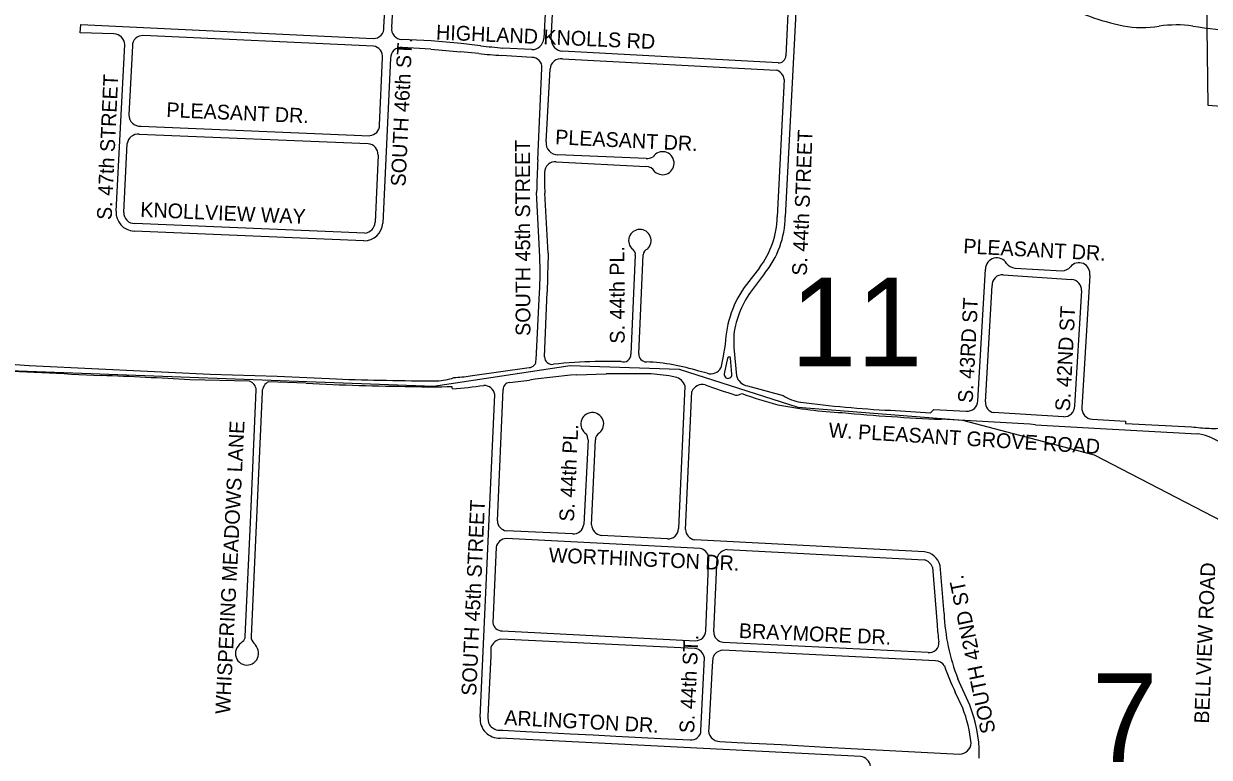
# Model space of a CAD drawing. Extents: x 0 to 712119, y 0 to 761125.
# Drawn here: x 668176 to 672194, y 717234 to 719721 of the extents above; entities that cross this region are included whole.
import ezdxf

# ---------------------------------------------------------------- set-up
doc = ezdxf.new("R2010")
doc.units = 0
for name, color, linetype in [('PAVED ROADS', 7, 'Continuous'), ('Priority 10', 7, 'Continuous'), ('Priority 11', 7, 'Continuous'), ('Priority 7', 7, 'Continuous'), ('street names', 7, 'Continuous')]:
    doc.layers.add(name, color=color, linetype=linetype)

msp = doc.modelspace()

# ---------------------------------------------------------------- linework, layer by layer
at = {"layer": 'PAVED ROADS'}
for points in [[(669397, 719709.4), (669403.4, 719825.1), (669409.6, 719943.3)], [(669423.3, 719708.6), (669436.1, 719940.9)], [(669951.4, 719905.7), (669938.5, 719670.6)], [(669963.9, 719668.3), (669975.8, 719905.8)], [(670795.5, 719831.4), (670791.3, 719737.7), (670757.2, 719066.8)], [(670769.2, 719827.4), (670759.6, 719612.3)], [(668481.8, 719686.4), (668368, 719690.6), (668369.4, 719718.6), (669360.9, 719671.4)], [(669361.5, 719644.8), (668581, 719680.8)], [(669556.9, 719663.2), (669457.9, 719667.3)], [(668489, 719085.5), (668519, 719650.2)], [(668544.5, 719646.3), (668532.6, 719412.3)], [(668544.5, 719646.3), (668544.5, 719646.3)], [(669556.2, 719635.2), (669459, 719640.1)], [(669718.6, 719619.8), (669657, 719626.1)], [(669724.8, 719646.3), (669659.2, 719653.9)], [(669898, 719633.6), (669800.2, 719637.9)], [(670733.1, 719588.5), (670002.2, 719627.7)], [(669382.2, 719376.8), (669391.9, 719605.6)], [(669419.3, 719603.8), (669392.9, 719044.7)], [(669898, 719606.4), (669795.6, 719613.4)], [(670002, 719601.7), (670726, 719563.8)], [(669918.4, 719259.3), (669932.2, 719570.8)], [(669946.7, 719320.5), (669960.1, 719567.8)], [(670753.7, 719531.7), (670730.1, 719066.4)], [(668567.6, 719346.5), (669343.2, 719314.4)], [(668573.6, 719373.9), (669349.2, 719341.5)], [(668515.6, 719081.5), (668527.2, 719314.5)], [(669377.1, 719275.4), (669367.4, 719047.8)], [(670285.3, 719264.1), (669986.3, 719277)], [(669981.2, 719253.3), (670284.9, 719237.4)], [(669925.5, 718930.3), (669914.2, 719149.3)], [(669953.8, 718943.7), (669942.5, 719146.9)], [(669329, 718984.6), (668550.1, 719017.8)], [(669332.7, 719011), (668552.2, 719044)], [(670248.9, 718936.7), (670233.9, 718601)], [(670240.1, 718956.3), (670240.1, 718956.3)], [(670261.1, 718602.3), (670275.5, 718937.8)], [(670670.2, 718893.8), (670625.8, 718837.5)], [(670686.6, 718874), (670645.8, 718820)], [(671410, 718442.8), (671435.2, 718889.4)], [(671496, 718869.9), (671727.6, 718853.6)], [(671535.1, 718892.6), (671696, 718883.8)], [(671788.9, 718867.9), (671762.2, 718420.6)], [(671435.7, 718438.9), (671458.2, 718833.1)], [(671761.1, 718816.3), (671737.9, 718425.5)], [(669912.4, 718581.8), (669924.7, 718809.9)], [(669941.1, 718591.9), (669950.3, 718810.7)], [(670583, 718667.9), (670583, 718623.3), (670591.3, 718527.6)], [(670554, 718634.2), (670545.5, 718588), (670538.6, 718555)], [(670200.6, 718575.5), (670112.9, 718575.9), (670112.9, 718575.9)], [(670561.6, 718587.8), (670550.4, 718534.2)], [(670576.6, 718532.7), (670571.5, 718587.2)], [(668808.3, 718533.2), (669035.2, 718526.3), (669235.9, 718516.8)], [(669688.9, 718527.1), (669888.8, 718555.5)], [(670049.1, 718531), (670150, 718534.7)], [(670492.7, 718536.3), (670464.4, 718543.6)], [(668941.6, 718509.1), (668739.4, 718514)], [(669133.9, 718502.4), (669006.3, 718507.6)], [(669822.6, 718504.3), (669890, 718513.1)], [(670417.3, 718492.4), (670395.4, 718009.4)], [(670628.6, 718493), (670749.6, 718460.9)], [(668926.5, 717644), (668944.7, 718029.8), (668964, 718479.5)], [(668984.2, 718473), (668947, 717643.5)], [(669723, 717369.7), (669772.3, 718464.5)], [(669781.4, 718035.7), (669800.8, 718481.4)], [(670418.9, 718006.6), (670440.4, 718474.8)], [(671249.8, 718401.8), (671260.5, 718413.4), (671370.6, 718407.9)], [(671113.5, 718410.5), (671249.8, 718401.8), (671249.8, 718401.8), (671249.8, 718401.8), (671249.8, 718401.8)], [(671699.8, 718388.7), (671463.2, 718402.6)], [(671797, 718380.6), (671909.7, 718373.4), (671910.4, 718365.6), (672134, 718354.3)], [(671605.7, 718361.8), (671785.3, 718351.4), (672152.6, 718330.7)], [(670088.9, 718310), (670074.2, 718023)], [(670100.9, 718022.4), (670113.5, 718310.6)], [(670468.9, 717942.5), (669811.5, 717976.2)], [(670036.1, 717991.5), (669811.7, 718002.1)], [(670357.8, 717975.2), (670133.1, 717986.7)], [(671228.7, 717930.9), (670450.1, 717971.1)], [(669777, 717946.2), (669765.6, 717690.3)], [(670560.2, 717938.4), (671227.7, 717903.7)], [(670488.2, 717663.3), (670498.4, 717912.6)], [(670514.6, 717659.4), (670525.8, 717912.2)], [(671255.6, 717879.2), (671271.6, 717683)], [(671295.4, 717722.2), (671281.6, 717885.1)], [(669797.4, 717662.6), (670453, 717629.4)], [(669797.4, 717662.6), (669797.4, 717662.6)], [(668914, 717623.5), (668918, 717627)], [(670451.2, 717603.3), (669793.5, 717635.2)], [(671240.9, 717589.9), (670547.1, 717624.1)], [(669759.8, 717606.5), (669759, 717577.3), (669749.5, 717374.7)], [(670471.5, 717325.1), (670482.9, 717572)], [(670511.5, 717571.4), (670509.6, 717543.8), (670497.9, 717332.7)], [(671266.2, 717561.9), (670544.2, 717597.1)], [(671382.2, 717410.7), (671342.1, 717500.8)], [(671358.5, 717401), (671333.2, 717455.4)], [(669787.7, 717325.9), (669800, 717325.9), (669878.1, 717322.1), (669945.4, 717318.7), (670029.3, 717314.1), (670106.1, 717310.4), (670183, 717305.8), (670334.9, 717298.4), (670434.3, 717293.4)], [(671012.7, 717237.1), (669791.1, 717299.1)], [(670535.9, 717288.1), (670594.2, 717284.9), (670668.8, 717281.7), (670743.7, 717277.3), (670818.9, 717273.1), (670893.1, 717268.9), (670980.9, 717264.8), (671347.3, 717245.3)], [(670535.9, 717288.1), (670535.9, 717288.1), (670535.9, 717288.1)]]:
    msp.add_lwpolyline(points, dxfattribs=at)
for centre, radius, start, end in [((672072.9, 720538.1), 841.7, 242.1615, 258.2988), ((669363, 719705.5), 34.2, 266.4728, 6.5311), ((669459.2, 719703.5), 36.3, 171.9329, 267.8384), ((671966.8, 720057), 349.2, 259.3393, 279.4982), ((672083.2, 719313.5), 403.4, 82.1403, 98.3758), ((672386.7, 721280), 1586.4, 260.9958, 266.6809), ((668480.1, 719647.4), 39.1, 4.1097, 87.4028), ((668579.6, 719645.8), 35.1, 87.7503, 179.0986), ((669250.5, 715746.1), 3929, 84.0292, 85.5278), ((669898.8, 719673.3), 39.8, 268.8332, 356.0572), ((670004, 719667.8), 40.1, 179.2599, 267.489), ((669357.4, 719610.2), 34.9, 352.3842, 83.2013), ((669454.8, 719604.8), 35.5, 83.3228, 181.6046), ((670126.7, 725423.7), 5816.5, 264.37163, 265.3677), ((669888.2, 721184.4), 1573.8, 263.8127, 266.6246), ((670873.6, 729634), 10053.5, 263.43886, 263.87095), ((669899.6, 719573.7), 32.7, 354.7849, 92.7415), ((669996.7, 719565.5), 36.6, 81.6269, 176.3044), ((670734.6, 719613.5), 25, 266.6118, 357.4416), ((670716.2, 719527.3), 37.8, 6.7363, 74.9993), ((668570.2, 719411.4), 37.7, 178.6619, 275.0855), ((669346.3, 719377.3), 35.9, 274.6012, 359.1598), ((668563.7, 719309.9), 36.8, 83.9311, 172.8665), ((669340.2, 719277.5), 37, 356.85, 85.2205), ((669986, 719316.4), 39.5, 173.9806, 270.5043), ((681511.5, 718755.3), 11604, 177.5108, 178.05438), ((670286.6, 719310.3), 46.2, 268.3597, 298.9214), ((670341.4, 719248.2), 39, 227.8607, 146.414), ((670489, 719189.8), 548.2, 177.1552, 184.489), ((669977.4, 719217.5), 36, 84.0452, 180.7246), ((670282.6, 719199.1), 38.4, 31.778, 86.6573), ((668553.7, 719082.5), 64.8, 177.3558, 266.8147), ((668550.5, 719078.9), 34.9, 175.7004, 272.812), ((670426.6, 719075), 303.6, 323.3638, 358.3665), ((670446.3, 719071.3), 310.9, 320.6177, 359.1673), ((669328.7, 719048.9), 64.3, 270.2466, 356.234), ((669328, 719050.1), 39.4, 276.8577, 356.5972), ((670264.3, 718985.6), 38, 311.9511, 230.3577), ((675761.7, 718725.8), 5812, 177.85112, 179.16277), ((670229.7, 718939.8), 19.5, 350.7912, 57.86), ((670297, 718937), 21.5, 109.6388, 177.9251), ((668349.4, 718881.1), 1576.8, 357.4136, 1.7873), ((671474.1, 718888.5), 38.8, 30.7742, 178.716), ((671540.3, 718933.9), 41.6, 217.8571, 262.8485), ((671693.7, 718923.1), 39.4, 273.4049, 318.7935), ((671752.2, 718873.7), 37.2, 351.1225, 140.8753), ((671493.2, 718835), 35.1, 85.4148, 183.0457), ((671725.7, 718818.2), 35.5, 356.9321, 86.9321), ((670911.9, 718622.2), 358.1, 143.0272, 178.0743), ((670901.6, 718625.3), 321.5, 142.7382, 172.3849), ((669888.5, 718579.5), 24, 270.5913, 5.5612), ((669967.1, 718592.3), 26, 180.9546, 280.7958), ((670145.3, 716985.7), 1590.5, 91.1664, 96.2536), ((670208.5, 718599.7), 25.4, 251.9083, 2.8477), ((670286.4, 718600.2), 25.4, 175.4256, 271.4098), ((670252.2, 717858.6), 717.1, 72.7876, 87.2153), ((670566.5, 718586.7), 5, 5.4395, 168.1853), ((671419.7, 781551.1), 63092.8, 266.925456, 267.292135), ((673192.1, 815630), 97195.7, 266.969225, 267.41493), ((670188.2, 699898.8), 18635.9, 89.64927, 90.11743), ((670252.2, 717860.3), 675.9, 78.7979, 85.7497), ((670504.8, 718572.4), 38.1, 251.4993, 332.7515), ((670563.4, 718531.9), 13.2, 170.1155, 3.3502), ((667766.6, 701844.5), 16697.8, 86.66034, 87.69228), ((668932, 718478.5), 32.1, 1.8514, 72.4659), ((669025.3, 718471.1), 41.2, 117.4813, 177.394), ((669565.3, 726803.2), 8312, 267.02509, 269.4911), ((669653, 731113), 12603.1, 268.10333, 269.64811), ((669566.3, 718720.6), 210.6, 272.5151, 288.7977), ((669538.1, 719814.5), 1334.2, 273.9457, 278.5076), ((669581.5, 719266.3), 746.9, 274.0422, 278.2656), ((669735.7, 718457.8), 37.3, 10.356, 90.27), ((669823.1, 718482), 22.3, 91.4674, 181.6696), ((670319.8, 715417), 3125.7, 94.9692, 97.904), ((670376.5, 718481.7), 42.2, 14.596, 80.4052), ((670475.8, 718459.4), 38.6, 75.8684, 156.5421), ((671104.1, 720180.8), 1794.1, 249.8188, 253.2997), ((670639.6, 718542.3), 50.4, 196.8531, 257.4165), ((669557.4, 720118.2), 1627.9, 267.6798, 272.4674), ((669571.9, 718470.8), 59.3, 12.3594, 20.6536), ((670592.9, 718488.8), 26.8, 260.6129, 307.9786), ((671030.6, 719606.5), 1214.2, 249.7035, 255.7649), ((670828.3, 718580.1), 142.8, 236.5432, 262.3616), ((671037.4, 720014.1), 1613.7, 259.0908, 266.9062), ((671290.5, 721998), 3591.8, 262.3017, 267.1756), ((671374.2, 718443.5), 35.8, 264.2247, 358.8052), ((671470.1, 718436.4), 34.5, 175.8848, 258.4246), ((671701.4, 718425.2), 36.6, 267.4898, 0.4249), ((671799.2, 718417.7), 37.1, 175.55, 266.6365), ((670103, 718364.2), 38.8, 308.6553, 238.5843), ((671573, 725093.1), 6719.2, 264.68298, 267.54375), ((670266.5, 697681.7), 20723.4, 86.29482, 87.18291), ((670139.8, 718310.8), 26.2, 118.4974, 180.3534), ((672266.1, 719672), 1324.3, 264.2743, 266.8847), ((672207.4, 718474.8), 125.8, 263.9548, 278.026), ((670051, 718310.3), 37.9, 359.4735, 33.09), ((672133.7, 718162.7), 169, 56.9121, 83.5796), ((669816.8, 718037.2), 35.4, 182.474, 261.759), ((670038.4, 718027.5), 36.1, 266.3784, 352.8996), ((670138, 718023.5), 37.1, 181.7032, 262.3206), ((669814, 717938.5), 37.8, 93.7317, 168.3239), ((670360.3, 718010.3), 35.2, 265.9355, 358.5882), ((670457.2, 718008.8), 38.4, 183.3362, 259.3579), ((670460.3, 717904.5), 39, 12.0156, 77.2765), ((670563.7, 717898.2), 40.3, 94.911, 159.7744), ((671221.9, 717869.4), 61.8, 14.6932, 83.6777), ((671220.7, 717867.6), 36.8, 18.4117, 78.9658), ((669799.1, 717696.6), 34.1, 190.6535, 267.2379), ((671965.9, 717748.1), 671, 182.2134, 201.6267), ((670453, 717664.7), 35.2, 270.0867, 357.7587), ((670550, 717659.4), 35.4, 179.962, 265.3145), ((671889.7, 717720.1), 619.2, 183.4298, 188.7826), ((668933, 717586.6), 39.4, 140.7502, 15.3461), ((668991.8, 717537.4), 116, 132.1119, 140.3259), ((668908.2, 717642.5), 18.3, 302.1835, 4.6864), ((668976.4, 717642.6), 29.4, 178.3185, 227.4626), ((668919.9, 717582.5), 53.1, 15.837, 46.441), ((669800.4, 717593), 42.8, 99.2687, 161.6953), ((671245.4, 717622.2), 32.6, 262.0484, 5.9069), ((670445.9, 717566.2), 37.5, 8.9639, 81.8685), ((670546.3, 717560.6), 36.5, 93.3, 162.7687), ((671265.9, 717526.9), 35, 29.6243, 89.5111), ((672381.9, 717942.6), 1156.4, 200.1529, 204.9164), ((670972.2, 717244.6), 442.4, 359.8399, 22.0491), ((669788.7, 717364.9), 65.9, 175.823, 272.0994), ((669804.9, 717367.8), 55.8, 172.8931, 204.7311), ((670928.2, 717235.1), 461.2, 5.9352, 21.0827), ((669790.9, 717371.3), 45.4, 216.1413, 265.8954), ((670534.5, 717325.4), 37.3, 168.7594, 272.1084), ((670438.2, 717326.4), 33.3, 263.241, 357.776), ((671347.9, 717284.3), 39, 269.1177, 357.6733), ((671008.3, 717200.1), 37.3, 5.1409, 83.166), ((671233.8, 717237.2), 180.8, 358.2077, 1.9767)]:
    msp.add_arc(centre, radius, start, end, dxfattribs=at)
at = {"layer": 'Priority 10'}
msp.add_lwpolyline([(672393.9, 719427.8), (672189.9, 719443.3), (672184.2, 719884.1), (670526.1, 720904.4), (670707.2, 721705), (670906.1, 721745.4), (670959.6, 721513.7), (670875.6, 720920.4), (672072.3, 720524.1), (672380.1, 719941.2)], close=True, dxfattribs=at)
at = {"layer": 'Priority 11'}
msp.add_lwpolyline([(668035.7, 718549.2), (669564.9, 718492.9), (670028.3, 718562.8), (670397.3, 718550), (670799.9, 718421.5), (671357.4, 718377.7), (671357.4, 718377.7), (671803.7, 718259.9), (672268.1, 718018.9)], dxfattribs=at)

# ---------------------------------------------------------------- texts
msp.add_text('11', height=300, dxfattribs=at).set_placement((670775.5, 718560.1))
at = {"layer": 'Priority 7'}
msp.add_text('7', height=300, dxfattribs=at).set_placement((671796.1, 717218.8))
at = {"layer": 'street names'}
for s, rotation, p in [('HIGHLAND KNOLLS RD', 357.5008, (669572.8, 719667.6)), ('SOUTH 46th ST.', 87.3762, (669470, 719168.5)), ('S. 47th STREET', 87.3762, (668474.1, 719054.9)), ('PLEASANT DR.', 357.5008, (668658.8, 719404.8)), ('PLEASANT DR.', 357.2421, (669976.5, 719312.5)), ('S. 44th STREET', 87.6716, (670829.9, 718866.1)), ('SOUTH 45th STREET', 90.173, (669893.5, 718662.7)), ('KNOLLVIEW WAY', 357.5008, (668570.5, 719066.7)), ('PLEASANT DR.', 357.0105, (671359.6, 718942.8)), ('S. 44th PL.', 90.173, (670213, 718636.5)), ('S. 43RD ST', 87.0105, (671392.1, 718434.7)), ('S. 42ND ST', 87.0105, (671721.6, 718406.4)), ('WHISPERING MEADOWS LANE', 87.1461, (668875.2, 717379.8)), ('S. 44th PL.', 87.3863, (670040.9, 718032.3)), ('W. PLEASANT GROVE ROAD', 356.4642, (670902.8, 718319.3)), ('SOUTH 45th STREET', 87.3863, (669709.5, 717442)), ('WORTHINGTON DR.', 357.4484, (669954.6, 717895.6)), ('BELLVIEW ROAD', 87.6518, (672192.8, 717348)), ('SOUTH 42ND ST.', 101.6991, (671470.2, 717320.8)), ('BRAYMORE DR.', 357.4484, (670599.2, 717639.1)), ('S. 44th ST.', 87.3863, (670448, 717315.2)), ('ARLINGTON DR.', 357.0105, (669804, 717344.8))]:
    msp.add_text(s, height=50, rotation=rotation, dxfattribs=at).set_placement(p)

doc.saveas('drawing.dxf')
